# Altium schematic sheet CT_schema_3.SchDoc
size 421 x 351 mm
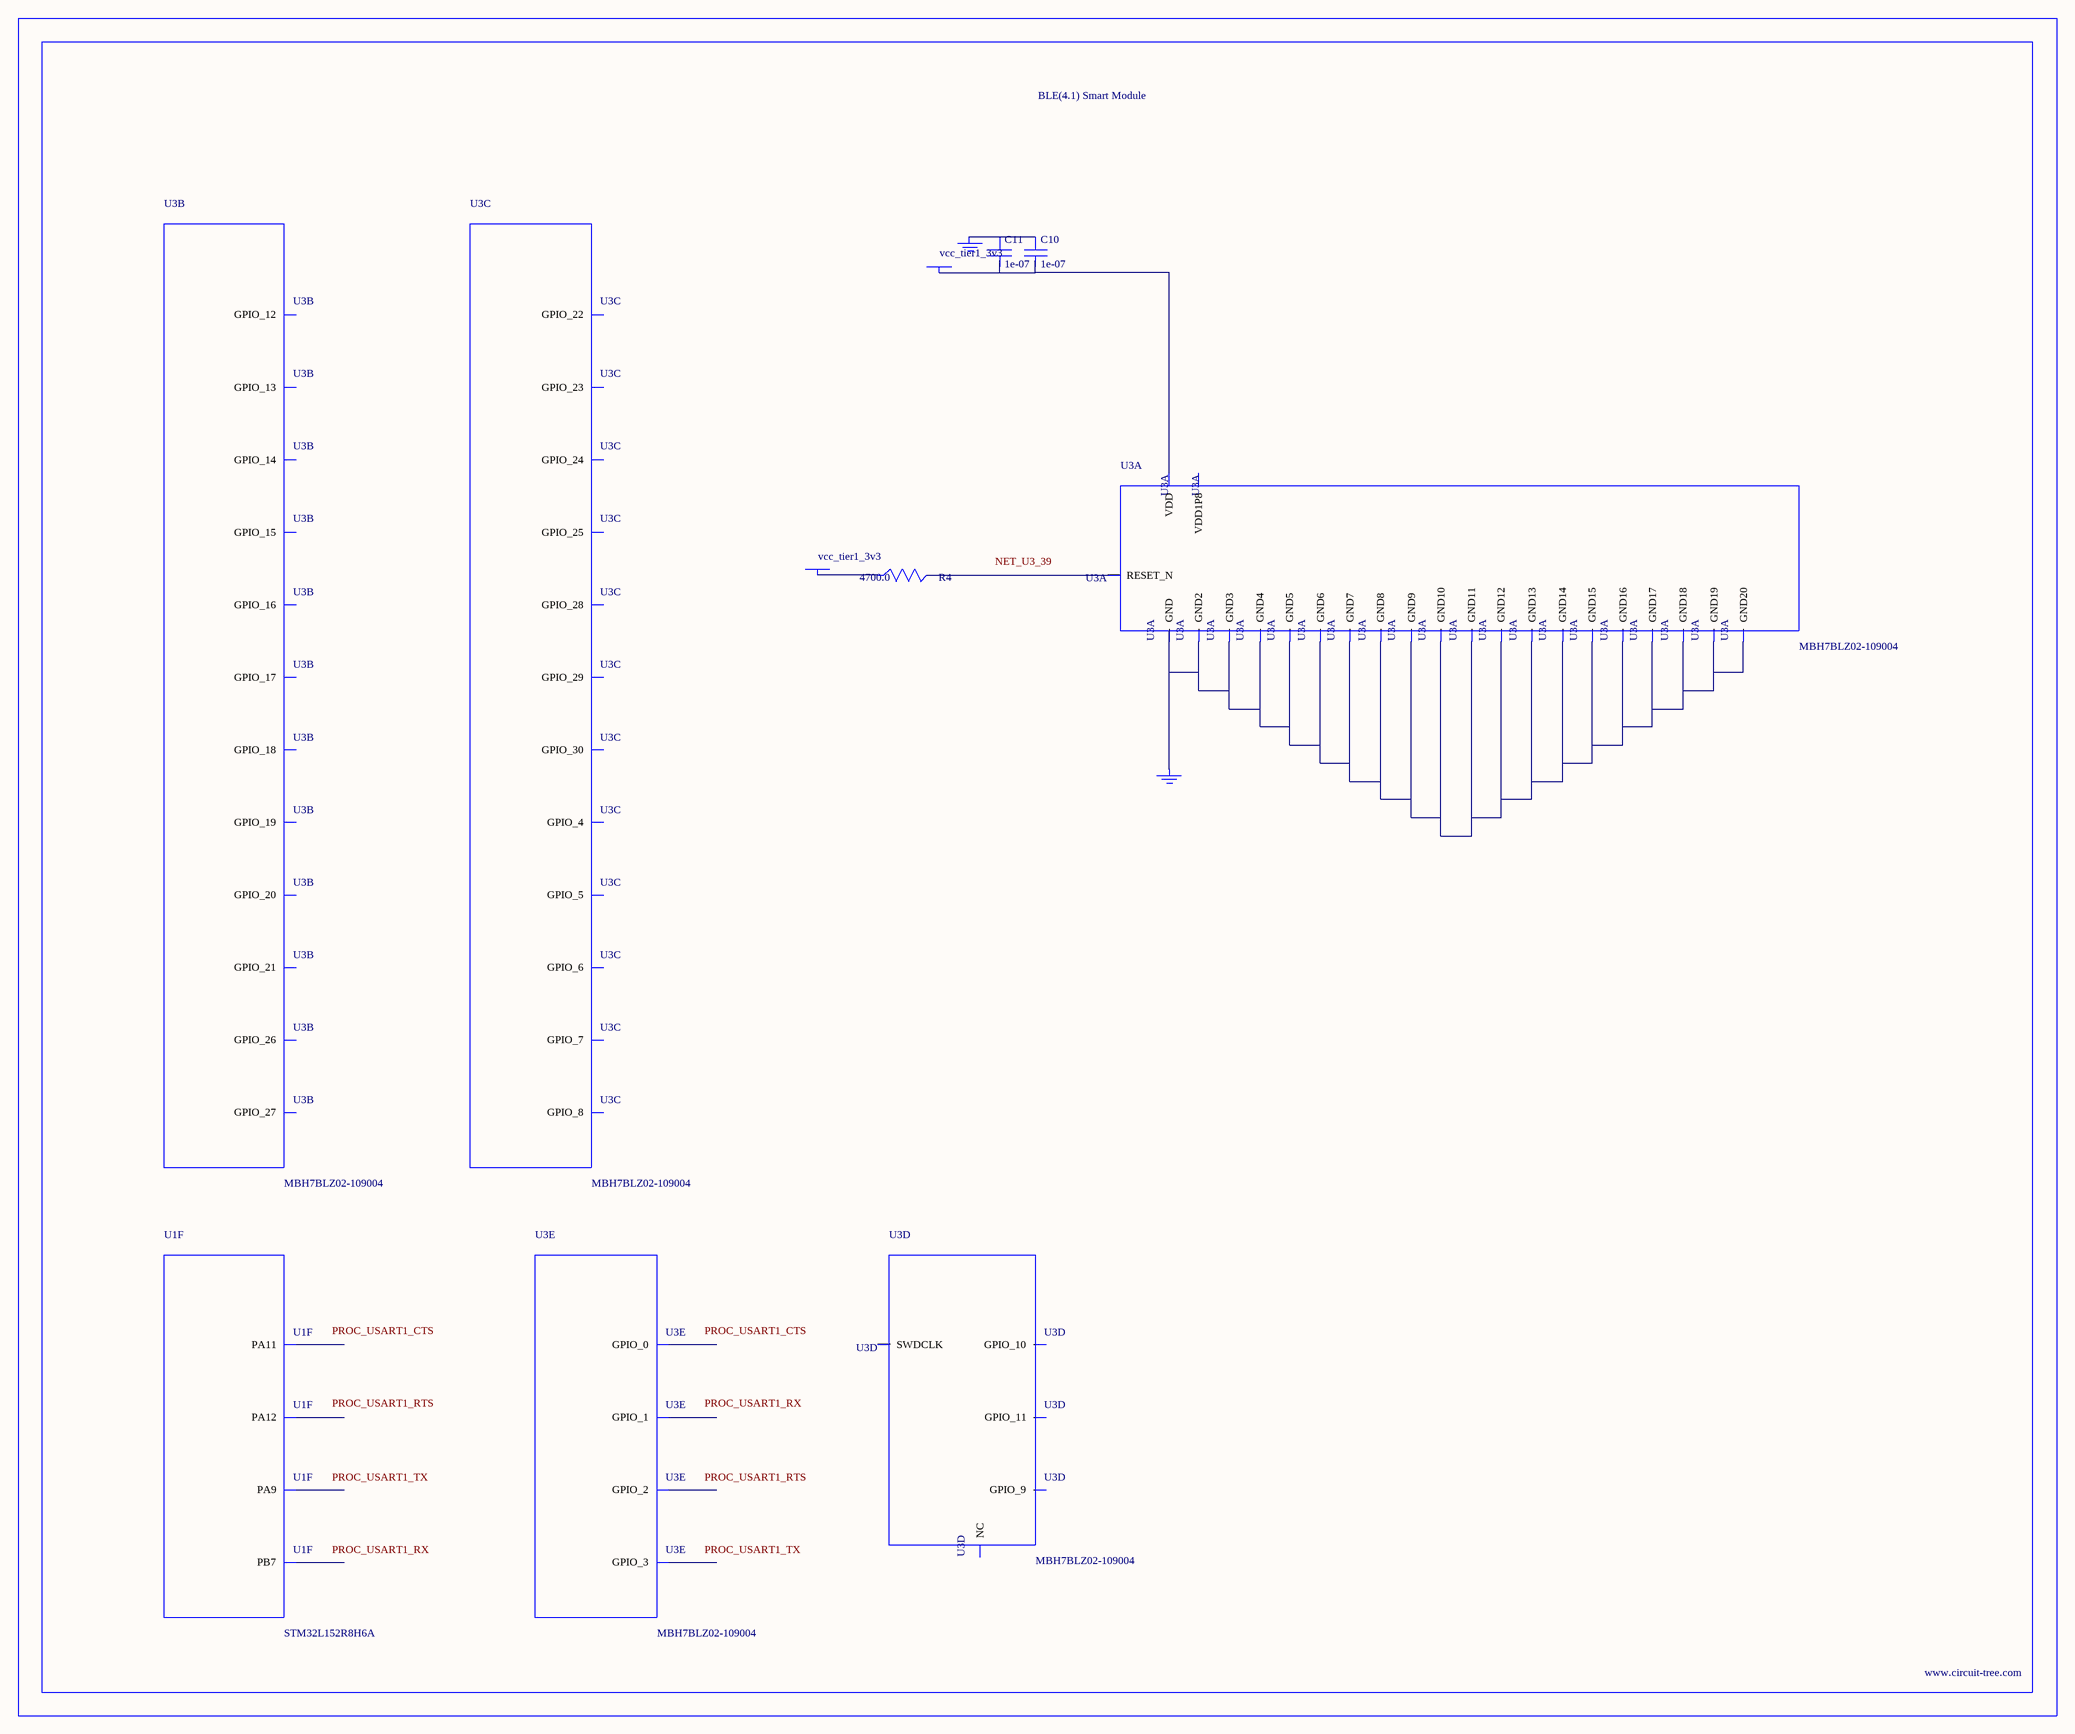
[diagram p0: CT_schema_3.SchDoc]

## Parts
BORDER2  (no value)
C10  1e-07  [C0402]
C11  1e-07  [C0402]
GND_INSTANCE_2_0  (no value)
GND_INSTANCE_2_1  (no value)
POWER_INSTANCE_2_0  vcc_tier1_3v3
POWER_INSTANCE_2_1  vcc_tier1_3v3
R4  4700.0  [R0603]
U1  STM32L152R8H6A  [TFBGA64]  (part F of 7)
U3  MBH7BLZ02-109004  [MBH7BLZ02-109004]  (parts A,B,C,D,E of 5)

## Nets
NetC10_1: C10.1 C11.1 GND_INSTANCE_2_0.0(GND)
NetC10_2: C10.2 C11.2 POWER_INSTANCE_2_0.0(PWR) U3.28(VDD)
NetGND_INSTANCE_2_1_0: GND_INSTANCE_2_1.0(GND) U3.1(GND) U3.3(GND2) U3.15(GND3) U3.27(GND4) U3.29(GND5) U3.41(GND6) U3.42(GND7) U3.43(GND8) U3.44(GND9) U3.45(GND10) U3.46(GND11) U3.47(GND12) U3.48(GND13) U3.49(GND14) U3.50(GND15) U3.52(GND16) U3.53(GND17) U3.54(GND18) U3.55(GND19) U3.56(GND20)
NetPOWER_INSTANCE_2_1_0: POWER_INSTANCE_2_1.0(PWR) R4.1
NetR4_2: R4.2 U3.39(RESET_N)

Not connected (* = marked no-connect by the designer): U1 B8(PA12) C3(PB7) C7(PA9) C8(PA11); U3 2(VDD1P8) 4(GPIO_17) 5(GPIO_19) 6(GPIO_18) 7(GPIO_20) 8(GPIO_16) 9(GPIO_15) 10(GPIO_14) 11(GPIO_13) 12(GPIO_12) 13(GPIO_27) 14(GPIO_26) 16(GPIO_21) 17(GPIO_22) 18(GPIO_23) 19(GPIO_24) 20(GPIO_6) 21(GPIO_5) 22(GPIO_4) 23(GPIO_3) 24(GPIO_2) 25(GPIO_1) 26(GPIO_0) 30(GPIO_25) 31(GPIO_29) 32(GPIO_28) 33(GPIO_30) 34(GPIO_7) 35(GPIO_8) 36(GPIO_9) 37(GPIO_10) 38(GPIO_11) 40(SWDCLK) 51(NC)

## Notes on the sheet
- Labels drawn without touching a wire or pin: NET_U3_39, PROC_USART1_CTS, PROC_USART1_RTS, PROC_USART1_RX, PROC_USART1_TX

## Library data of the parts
BORDER2 = BORDER_PAGE2
C10 C11 = C0402C104K3RACTU
GND_INSTANCE_2_0 GND_INSTANCE_2_1 = GND
POWER_INSTANCE_2_0 POWER_INSTANCE_2_1 = PWR
R4 = RC0603JR-074K7L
